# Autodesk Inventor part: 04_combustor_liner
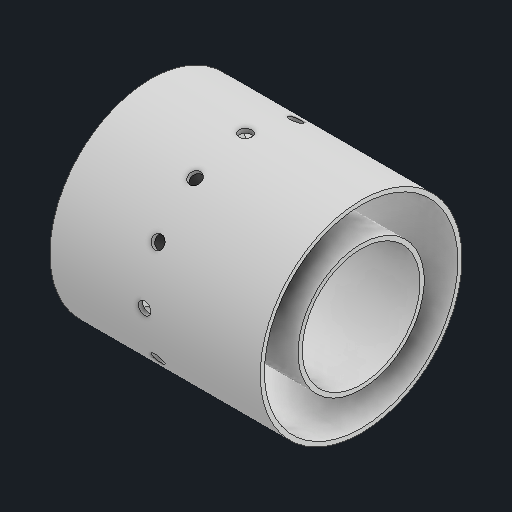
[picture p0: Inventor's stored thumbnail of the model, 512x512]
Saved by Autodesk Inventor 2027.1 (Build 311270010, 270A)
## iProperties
Created: 2026-10
Part Number: 04_combustor_liner
Material: Generic
Document SubType Name: Modeling
Designer: BHAVAN KUMAR
Density: 1 g/cm^3
Appearance: Default
Author: BHAVAN KUMAR
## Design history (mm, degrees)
sketch "Sketch1"
  geometry: L1 (0, 0)-(38.928, 0); L2 (0, 48)-(100, 48); L3 (100, 48)-(100, 46); L4 (100, 46)-(12, 46); L5 (12, 46)-(12, 30); L6 (12, 30)-(100, 30); L7 (100, 30)-(100, 28); L8 (100, 28)-(0, 28); L9 (0, 28)-(0, 48)
  constraints: 18 end point, 6 perpendicular, 2 horizontal, 2 point on line
  dimensions: "d0" = 100 distance of L2.start L2.end; "d1" = 2 distance of L2.end L3.end; "d2" = 88 distance of L3.end L4.end; "d3" = 16 distance of L4.end L5.end; "d4" = 2 distance of L6.end L7.end; "d5" = 0 distance from line of L1.start L9; "d6" = 28 distance from line of L1.start L8
revolve "Revolution1" sketch "Sketch1" stored, may be unused: angle "d7" = 90 deg
sketch "Sketch2"
  geometry: L1 (9.6, 0)-(-57.6, 0) reference; L2 (0, 28)-(0, -28) reference; C1 r 3 at (-45, 0); 1 further point
  constraints: 1 centre point
  dimensions: "d8" = 6 diameter of C1; "d9" = 0 distance from line of L1 C1.centre; "d10" = 45 distance from line of C1.centre L2
extrude "Extrusion1" cut sketch "Sketch2" extent not by distance; stored distance "d11" = 0; taper "d12" = 0 deg
pattern_circular "Circular Pattern1" dims angle "d14" = 360 deg
sketch "Sketch5"
  geometry: C1 r 2.5 at (38, 0)
  constraints: 1 centre point
  dimensions: "d28" = 5 diameter of C1 (= inj_dia)
extrude "Injector_Hole" cut sketch "Sketch5" extent not by distance; stored distance "d29" = 0.13; taper "d30" = 0 deg
pattern_circular "Injector_Pattern" dims angle "d32" = 360 deg
body "Solid1"
other parameters: "liner_or" = 48 [user parameter], "liner_ir" = 28 [user parameter], "liner_t" = 2 [user parameter], "dome_t" = 2 [user parameter], "dil_dia" = 6 [user parameter], "dil_x" = 45 [user parameter], "inj_dia" = 5 [user parameter; used in 1 equation term], "inj_pcr" = 38 [user parameter]
